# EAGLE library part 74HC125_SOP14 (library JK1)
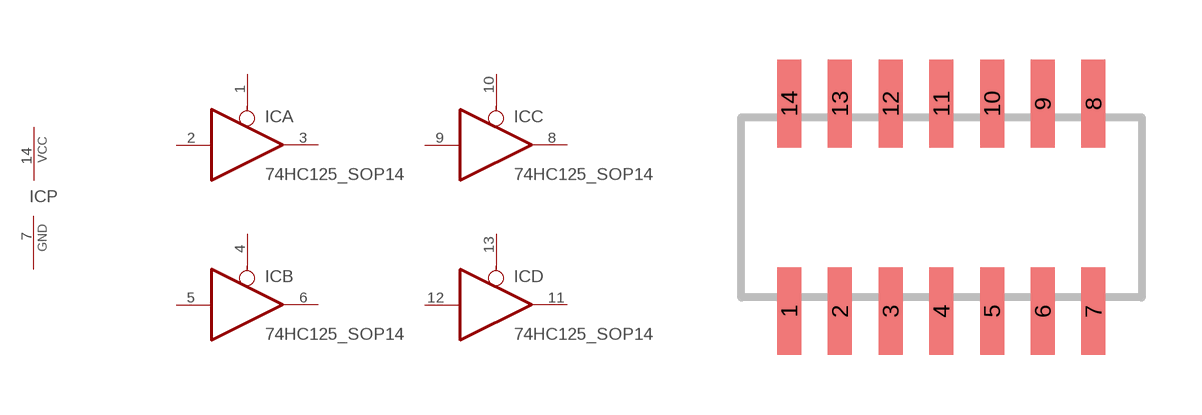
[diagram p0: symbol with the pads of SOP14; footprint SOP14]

Designator prefix IC; gates A=74125 B=74125 C=74125 D=74125 P=PWRN

## 74HC125_SOP14  [SOP14]
1  A:OE  in
2  A:I  in
3  A:O  hiz
4  B:OE  in
5  B:I  in
6  B:O  hiz
7  P:GND  pwr
8  C:O  hiz
9  C:I  in
10  C:OE  in
11  D:O  hiz
12  D:I  in
13  D:OE  in
14  P:VCC  pwr

## Footprint SOP14 (pad centres in mm)
smd 0.6 x 2.2: 1 -3.81,-2.6; 2 -2.54,-2.6; 3 -1.27,-2.6; 4 0,-2.6; 5 1.27,-2.6; 6 2.54,-2.6; 7 3.81,-2.6; 8 3.81,2.6; 9 2.54,2.6; 10 1.27,2.6; 11 0,2.6; 12 -1.27,2.6; 13 -2.54,2.6; 14 -3.81,2.6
